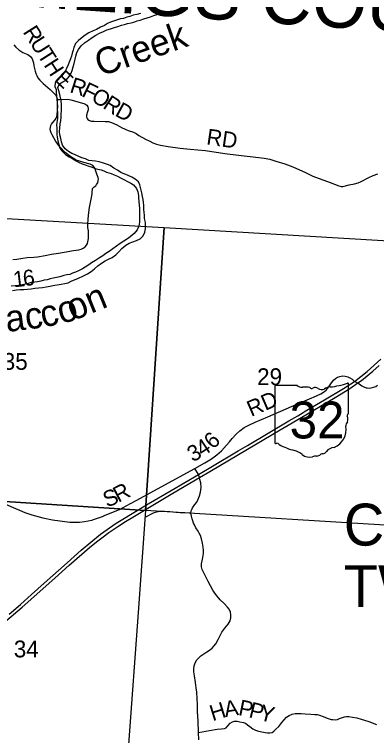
# Model space of a CAD drawing. Extents: x 0 to 34, y 0 to 22.
# Drawn here: x 4.807 to 6.101, y 18.062 to 20.64 of the extents above; entities that cross this region are included whole.
import ezdxf

# ---------------------------------------------------------------- set-up
doc = ezdxf.new("R2010")
doc.units = 0
for name, color, linetype in [('GM_X_Corporation', 7, 'Continuous'), ('GM_X_County_Road', 7, 'Continuous'), ('GM_X_County_Road_Text', 7, 'Continuous'), ('GM_X_County_Text', 7, 'Continuous'), ('GM_X_Major_River', 7, 'Continuous'), ('GM_X_Major_River_Text', 7, 'Continuous'), ('GM_X_Section_Text', 7, 'Continuous'), ('GM_X_State_Location', 7, 'Continuous'), ('GM_X_State_Route', 7, 'Continuous'), ('GM_X_State_Shield', 7, 'Continuous'), ('GM_X_Township_Road', 7, 'Continuous'), ('GM_X_Township_Road_Text', 7, 'Continuous'), ('GM_X_Township_Text', 7, 'Continuous')]:
    doc.layers.add(name, color=color, linetype=linetype)

msp = doc.modelspace()

# ---------------------------------------------------------------- linework, layer by layer
at = {"layer": 'GM_X_Corporation'}
for points in [[(5.342, 19.878), (5.2756, 18.8667), (4.2512, 18.9319), (4.3184, 19.9368)], [(6.3643, 19.8173), (6.291, 18.8048), (6.2863, 18.8051), (5.2756, 18.8667), (5.342, 19.878)], [(4.2512, 18.9319), (5.2756, 18.8667), (5.2491, 18.5021), (5.2146, 18.0305), (5.1989, 17.8285), (4.1811, 17.9012)]]:
    msp.add_lwpolyline(points, close=True, dxfattribs=at)
at = {"layer": 'GM_X_County_Road'}
msp.add_line((5.4645, 18.9957), (5.4516, 19.0172), dxfattribs=at)
for points in [[(5.8753, 19.272), (5.901, 19.2832), (5.9115, 19.2892), (5.9204, 19.2968), (5.9299, 19.3082), (5.9378, 19.3192), (5.9464, 19.3318), (5.9535, 19.3382), (5.9613, 19.3429), (5.9694, 19.3458), (5.9787, 19.3473), (5.9882, 19.3472), (5.9977, 19.3446), (6.0057, 19.3411), (6.013, 19.3358), (6.0224, 19.3279), (6.0334, 19.3224), (6.0481, 19.3119), (6.0549, 19.308), (6.0629, 19.3055), (6.0675, 19.3045), (6.0745, 19.3043), (6.0819, 19.3045), (6.0898, 19.3068), (6.0981, 19.3103), (6.1045, 19.3142)], [(5.5756, 19.1123), (5.5848, 19.1233), (5.5988, 19.139), (5.612, 19.1518), (5.6279, 19.1632), (5.6443, 19.1719), (5.6668, 19.1822), (5.7124, 19.2016), (5.7971, 19.2386), (5.8698, 19.2696), (5.8753, 19.272)], [(5.1256, 18.847), (5.182, 18.8697), (5.222, 18.891), (5.2441, 18.9036), (5.3055, 18.937), (5.4516, 19.0172), (5.4877, 19.0368), (5.5108, 19.0506), (5.5302, 19.0655), (5.5465, 19.0797), (5.5651, 19.0998), (5.5756, 19.1123)], [(4.7752, 18.8893), (4.8104, 18.8742), (4.8251, 18.8672), (4.8436, 18.8596), (4.8692, 18.8513), (4.9081, 18.8406), (4.943, 18.8337), (5.0054, 18.8244), (5.0211, 18.8242), (5.0396, 18.8244), (5.0574, 18.8267), (5.0834, 18.8321), (5.0929, 18.8354), (5.1247, 18.8467), (5.1256, 18.847)]]:
    msp.add_lwpolyline(points, dxfattribs=at)
at = {"layer": 'GM_X_Major_River'}
for points in [[(5.2579, 20.6426), (5.2439, 20.6395), (5.2314, 20.6368), (5.2197, 20.6326), (5.2091, 20.6296), (5.1962, 20.6257), (5.1864, 20.6238), (5.1501, 20.6116), (5.1395, 20.607), (5.1285, 20.6005), (5.1145, 20.594), (5.0998, 20.586), (5.0888, 20.5807), (5.0733, 20.5738), (5.0601, 20.5662), (5.0491, 20.5578), (5.0363, 20.5468), (5.0246, 20.5358), (5.0197, 20.521), (5.017, 20.5115), (5.0137, 20.5016), (5.011, 20.491), (5.0076, 20.4815), (5.0031, 20.4694), (4.999, 20.4599), (4.9933, 20.4462), (4.9865, 20.4344), (4.9767, 20.4207), (4.9639, 20.4086), (4.9526, 20.3953), (4.9515, 20.3816), (4.9556, 20.3714), (4.9564, 20.3615), (4.9568, 20.3487), (4.958, 20.3358), (4.9595, 20.3233), (4.9599, 20.3134), (4.96, 20.3009), (4.9604, 20.2884), (4.9604, 20.2679), (4.9589, 20.2531), (4.9578, 20.2436), (4.9582, 20.2342), (4.959, 20.2243), (4.9586, 20.2103), (4.9594, 20.2008), (4.9621, 20.1875), (4.9652, 20.1743), (4.9697, 20.1614), (4.9769, 20.1516), (4.9895, 20.1387), (5.002, 20.1308), (5.0156, 20.1232), (5.0274, 20.1165), (5.038, 20.1108), (5.049, 20.1059), (5.0596, 20.1018), (5.0725, 20.0969), (5.0842, 20.0939), (5.0956, 20.0894), (5.1054, 20.0867), (5.1164, 20.0837), (5.1266, 20.0807), (5.1365, 20.0762), (5.1524, 20.0709), (5.1634, 20.0668), (5.1755, 20.0611), (5.1857, 20.0559), (5.1982, 20.0495)], [(5.2501, 20.0416), (5.2384, 20.0511), (5.2259, 20.0579), (5.2137, 20.0635), (5.1872, 20.0748), (5.1751, 20.0828), (5.1622, 20.0903), (5.1489, 20.0994), (5.1391, 20.1035), (5.125, 20.1084), (5.1095, 20.1133), (5.0963, 20.1155), (5.0845, 20.1159), (5.0732, 20.1177), (5.061, 20.123), (5.0482, 20.1275), (5.0353, 20.1328), (5.0216, 20.1388), (5.0122, 20.1429), (4.9997, 20.1497), (4.9879, 20.1588), (4.9792, 20.172), (4.9746, 20.1838), (4.9727, 20.1967), (4.9696, 20.2088), (4.9685, 20.2217), (4.9688, 20.2334), (4.9707, 20.2486), (4.9722, 20.2596), (4.974, 20.2729), (4.9744, 20.2843), (4.9751, 20.2949), (4.9755, 20.3051), (4.9747, 20.318), (4.9735, 20.3309), (4.9689, 20.3536), (4.9655, 20.3665), (4.9617, 20.379), (4.9677, 20.3915), (4.9798, 20.3984), (4.9915, 20.4052), (5.0025, 20.4174), (5.0093, 20.4303), (5.0127, 20.4398), (5.0168, 20.4527), (5.0205, 20.4645), (5.0269, 20.4903), (5.0303, 20.5036), (5.036, 20.5146), (5.0454, 20.5271), (5.0575, 20.5381), (5.0711, 20.548), (5.0843, 20.5575), (5.0976, 20.5652), (5.1112, 20.5724), (5.1252, 20.5789), (5.1376, 20.5846), (5.1505, 20.5884), (5.1649, 20.5927), (5.1762, 20.5969), (5.1898, 20.6011), (5.2, 20.6037), (5.2114, 20.6072), (5.2235, 20.6099), (5.2333, 20.6126), (5.2454, 20.6171), (5.2564, 20.6198), (5.2689, 20.6237), (5.2814, 20.6271), (5.2935, 20.6313), (5.3048, 20.6355), (5.3169, 20.639), (5.3294, 20.6432)], [(5.1982, 20.0495), (5.2111, 20.0427), (5.2229, 20.0363), (5.2323, 20.0302), (5.243, 20.0174), (5.2475, 20.006), (5.2498, 19.9931), (5.2506, 19.9836), (5.2518, 19.9715), (5.2529, 19.9579), (5.2533, 19.9469), (5.2538, 19.9332), (5.2538, 19.8976), (5.2512, 19.8832), (5.2456, 19.8703), (5.235, 19.857), (5.221, 19.8444), (5.2104, 19.8379), (5.1843, 19.8204), (5.1715, 19.8113), (5.159, 19.8014), (5.1454, 19.7927), (5.1337, 19.785), (5.1224, 19.7763), (5.111, 19.7698), (5.0963, 19.7607), (5.0823, 19.7519), (5.0725, 19.7451), (5.06, 19.7367), (5.0502, 19.7306), (5.0354, 19.723), (5.0252, 19.7184), (5.015, 19.7149), (5.0052, 19.7104), (4.9938, 19.7084), (4.9836, 19.7061), (4.9688, 19.7019), (4.9579, 19.6996), (4.9458, 19.6969), (4.9352, 19.6946), (4.9238, 19.6916), (4.9132, 19.6893), (4.9011, 19.6866), (4.8898, 19.6843), (4.8799, 19.6831), (4.8671, 19.6812), (4.8561, 19.6785), (4.8402, 19.6746), (4.8296, 19.6723), (4.8198, 19.6708), (4.8092, 19.6692), (4.7955, 19.6681)], [(4.8005, 19.6533), (4.8141, 19.6552), (4.827, 19.6564), (4.8402, 19.6568), (4.8539, 19.6572), (4.8667, 19.6588), (4.88, 19.6607), (4.8925, 19.6619), (4.9076, 19.6642), (4.9208, 19.6662), (4.9341, 19.6685), (4.9447, 19.6708), (4.9734, 19.6754), (4.9867, 19.6781), (4.9995, 19.6804), (5.0098, 19.6857), (5.0237, 19.6918), (5.0336, 19.696), (5.054, 19.7052), (5.068, 19.7121), (5.0808, 19.7204), (5.0929, 19.7303), (5.105, 19.741), (5.1179, 19.7505), (5.1315, 19.7589), (5.1432, 19.765), (5.1561, 19.7703), (5.1689, 19.7802), (5.1802, 19.7909), (5.1908, 19.803), (5.2052, 19.8144), (5.2169, 19.8217), (5.2301, 19.8274), (5.2426, 19.832), (5.2559, 19.8373), (5.2664, 19.848), (5.2732, 19.8609), (5.2755, 19.8738), (5.2758, 19.8832), (5.2747, 19.8958), (5.2716, 19.9098), (5.2712, 19.9227), (5.2708, 19.9321), (5.2696, 19.9424), (5.2692, 19.9575), (5.2681, 19.9678), (5.2665, 19.978), (5.2646, 19.989), (5.2616, 20.0019), (5.2589, 20.0166), (5.2551, 20.0303), (5.2501, 20.0416)]]:
    msp.add_lwpolyline(points, dxfattribs=at)
at = {"layer": 'GM_X_State_Route'}
for points in [[(4.7883, 18.4958), (4.8282, 18.531), (4.8682, 18.5663), (4.9136, 18.6072), (4.995, 18.6797), (5.046, 18.7247), (5.0796, 18.7535), (5.1144, 18.7813), (5.1706, 18.8216), (5.1889, 18.8325), (5.2852, 18.89), (5.3667, 18.9378), (5.4645, 18.9957), (5.514, 19.0248), (5.6068, 19.0801), (5.6395, 19.099), (5.7872, 19.1867), (5.8197, 19.2052), (5.8287, 19.2112), (5.8517, 19.2248), (5.9148, 19.262), (5.982, 19.3023), (6.0224, 19.3279), (6.067, 19.3632), (6.1157, 19.408)], [(5.4683, 18.9843), (5.5047, 19.0058), (5.6072, 19.0664), (5.7568, 19.1545), (5.8482, 19.2086), (5.9525, 19.2702), (6.0054, 19.3027), (6.0334, 19.3224), (6.0463, 19.3315), (6.0665, 19.3473), (6.087, 19.3643), (6.1094, 19.3847)], [(4.2081, 18.3662), (4.3931, 18.3837), (4.5176, 18.395), (4.5827, 18.4009), (4.6096, 18.4044), (4.6234, 18.4073), (4.6449, 18.411), (4.6841, 18.4225), (4.7244, 18.4397), (4.7534, 18.4558), (4.7801, 18.4743), (4.8348, 18.5208), (4.9519, 18.6244), (5.0029, 18.6705), (5.0757, 18.7346), (5.1002, 18.7546), (5.1243, 18.7729), (5.1439, 18.7876), (5.1801, 18.8119), (5.2033, 18.8272), (5.2305, 18.8431), (5.3733, 18.9281), (5.4683, 18.9843)], [(5.4415, 18.8722), (5.4432, 18.8758), (5.4518, 18.888), (5.4582, 18.8968), (5.4635, 18.9072), (5.4687, 18.919), (5.4717, 18.9315), (5.4738, 18.949), (5.4723, 18.9649), (5.4696, 18.9774), (5.4683, 18.9843), (5.4645, 18.9957)], [(5.4654, 18.0462), (5.4648, 18.0726), (5.4631, 18.1142), (5.4615, 18.1468), (5.4609, 18.1736), (5.4599, 18.1933), (5.4585, 18.2168), (5.4564, 18.2327), (5.4542, 18.2517), (5.4497, 18.2757), (5.4487, 18.2825), (5.4483, 18.29), (5.4481, 18.3006), (5.4495, 18.3108), (5.4529, 18.3222), (5.4587, 18.3324), (5.4672, 18.3414), (5.4731, 18.3469), (5.4941, 18.3608), (5.5043, 18.3669), (5.5131, 18.3742), (5.5194, 18.381), (5.526, 18.3895), (5.5345, 18.4059), (5.5427, 18.4226), (5.5484, 18.432), (5.5586, 18.4454), (5.5707, 18.46), (5.5778, 18.4721), (5.5802, 18.483), (5.5804, 18.493), (5.5786, 18.5029), (5.5741, 18.5142), (5.5684, 18.5215), (5.5562, 18.5335), (5.5419, 18.5476), (5.5309, 18.5599), (5.5225, 18.5713), (5.5154, 18.5817), (5.4992, 18.6121), (5.4819, 18.6455), (5.4776, 18.6561), (5.4758, 18.6649), (5.4752, 18.6763), (5.4772, 18.6869), (5.4797, 18.6985), (5.4823, 18.7124), (5.4829, 18.723), (5.4815, 18.7355), (5.4789, 18.7495), (5.4748, 18.7654), (5.4713, 18.7767), (5.4672, 18.7856), (5.4635, 18.7928), (5.4556, 18.8046), (5.4497, 18.8152), (5.4466, 18.8215), (5.4438, 18.8293), (5.4417, 18.8364), (5.4391, 18.8468), (5.4377, 18.8571), (5.4385, 18.8658), (5.4415, 18.8722)]]:
    msp.add_lwpolyline(points, dxfattribs=at)
at = {"layer": 'GM_X_State_Shield'}
for p, q in [((5.7369, 19.3101), (5.7369, 19.1099)), ((5.8167, 19.3135), (5.7395, 19.3135)), ((6.0006, 19.2138), (6.0006, 19.3185)), ((6.0006, 19.2138), (6.0006, 19.2138))]:
    msp.add_line(p, q, dxfattribs=at)
for centre, radius, start, end in [((5.74, 19.3105), 0.00305, 98.1301, 188.1301), ((5.8351, 19.3367), 0.0296, 231.6195, 271.1119), ((5.9067, 19.5863), 0.2796, 275.8445, 288.9065), ((5.9977, 19.3189), 0.00294, 351.8621, 97.738), ((5.845, 19.2012), 0.1064, 80.4867, 94.9883), ((5.8691, 19.3115), 0.00855, 219.7921, 297.1024), ((5.8816, 19.2884), 0.0178, 54.4667, 119.1411), ((5.9046, 19.3201), 0.0214, 233.8562, 294.8282), ((5.9423, 19.2524), 0.0563, 97.3462, 120.7689), ((5.9999, 19.2061), 0.00454, 107.944, 210.337), ((5.9975, 19.2134), 0.00314, 289.6038, 7.7341), ((6.0111, 19.17), 0.0198, 136.8065, 186.9296), ((5.971, 19.1929), 0.0273, 340.033, 23.6496), ((5.9223, 19.1567), 0.0699, 292.3089, 8.9858), ((5.74, 19.1095), 0.00308, 171.9584, 258.3066), ((5.7404, 19.13), 0.0235, 267.339, 280.6039), ((5.7453, 19.0984), 0.00848, 29.7484, 93.2717), ((5.8523, 19.2782), 0.2019, 240.4129, 257.1985), ((5.7921, 19.02), 0.0632, 47.1842, 75.836), ((5.9033, 19.0906), 0.0226, 282.8732, 323.2771), ((5.9518, 19.0538), 0.0383, 94.4031, 142.5768), ((5.8604, 19.0974), 0.0401, 230.7004, 286.2918), ((5.8836, 19.0282), 0.0329, 85.6951, 111.2099), ((5.8865, 19.0824), 0.0214, 268.777, 315.5493), ((5.9059, 19.063), 0.00601, 65.7517, 132.6484)]:
    msp.add_arc(centre, radius, start, end, dxfattribs=at)
at = {"layer": 'GM_X_Township_Road'}
for points in [[(4.8051, 20.5316), (4.8119, 20.5227), (4.8222, 20.5135), (4.837, 20.5038), (4.8547, 20.4961), (4.8639, 20.4894), (4.87, 20.4809), (4.8729, 20.4736), (4.8746, 20.4664), (4.8769, 20.4558), (4.8808, 20.4369), (4.8829, 20.4288), (4.8866, 20.421), (4.8909, 20.4136), (4.8983, 20.4042), (4.9092, 20.3924), (4.9341, 20.371), (4.9453, 20.3606), (4.9534, 20.3523), (4.9562, 20.3488), (4.9576, 20.3447), (4.9613, 20.3362), (4.9686, 20.336), (4.9968, 20.3366), (5.0083, 20.3347), (5.0379, 20.3264), (5.0587, 20.3204), (5.0655, 20.3156), (5.0689, 20.3099), (5.0702, 20.304), (5.0699, 20.2989), (5.0675, 20.2913), (5.0641, 20.2802), (5.0647, 20.2724), (5.0664, 20.2676), (5.0692, 20.2642), (5.0732, 20.2614), (5.0811, 20.2587), (5.0924, 20.2577), (5.1312, 20.257), (5.1429, 20.2567), (5.1533, 20.2536), (5.1727, 20.2451), (5.1897, 20.236), (5.2028, 20.2294), (5.2137, 20.2247), (5.2322, 20.2189), (5.2424, 20.2139), (5.2517, 20.2066), (5.2754, 20.1938), (5.2904, 20.1867), (5.3019, 20.1812), (5.3145, 20.1763), (5.3291, 20.1723), (5.3557, 20.1676), (5.3996, 20.1618), (5.435, 20.1578), (5.4901, 20.153), (5.5581, 20.1427), (5.6078, 20.1362), (5.6803, 20.1282), (5.6997, 20.1258), (5.7193, 20.1222), (5.7409, 20.1158), (5.7734, 20.106), (5.8021, 20.0945), (5.847, 20.0753), (5.8728, 20.0618), (5.9347, 20.0392), (5.9653, 20.027), (5.9742, 20.0251), (5.9804, 20.025), (6.0028, 20.0305), (6.0215, 20.0341), (6.0348, 20.0375), (6.0462, 20.0427), (6.0725, 20.0572), (6.0885, 20.0641), (6.1048, 20.0698)], [(4.8017, 19.7637), (4.8162, 19.7645), (4.8368, 19.768), (4.8529, 19.7703), (4.8764, 19.772), (4.8896, 19.7733), (4.917, 19.7779), (4.9394, 19.7828), (4.9643, 19.7864), (4.9843, 19.7895), (5.0182, 19.7959), (5.0376, 19.7987), (5.0457, 19.8008), (5.0521, 19.8038), (5.0599, 19.8088), (5.0646, 19.8146), (5.0678, 19.8211), (5.0698, 19.8271), (5.0714, 19.8392), (5.0721, 19.8533), (5.0714, 19.8663), (5.0698, 19.8782), (5.0691, 19.8904), (5.0701, 19.9064), (5.0715, 19.9218), (5.0749, 19.9497), (5.0795, 19.973), (5.0796, 19.9737), (5.0832, 19.9914), (5.0842, 20.0002), (5.0846, 20.0067), (5.0855, 20.0127), (5.0864, 20.017), (5.0883, 20.0203), (5.0924, 20.0235), (5.0973, 20.0269), (5.1007, 20.0315), (5.1044, 20.038), (5.1067, 20.0456), (5.1074, 20.0509), (5.1063, 20.0574), (5.1012, 20.0689), (5.0975, 20.0795), (5.0957, 20.0876), (5.0924, 20.094), (5.0869, 20.0994), (5.0779, 20.1042), (5.0546, 20.1104), (5.0281, 20.1192), (5.008, 20.1303), (4.9887, 20.1462), (4.9703, 20.1653), (4.9546, 20.1861), (4.9416, 20.2095), (4.9379, 20.217), (4.9363, 20.2241), (4.9352, 20.2301), (4.9357, 20.2358), (4.9368, 20.2425), (4.9398, 20.2478), (4.9437, 20.2536), (4.9523, 20.2626), (4.9567, 20.2688), (4.9583, 20.2739), (4.9598, 20.282), (4.9608, 20.2958), (4.9615, 20.3105), (4.9613, 20.3239), (4.9613, 20.3362)], [(5.4377, 18.8571), (5.4153, 18.8576), (5.3986, 18.8576), (5.3833, 18.8595), (5.3744, 18.8603), (5.3618, 18.8618), (5.3433, 18.8625), (5.332, 18.8625), (5.3204, 18.8618), (5.31, 18.8595), (5.3029, 18.8571), (5.295, 18.8536), (5.2824, 18.8467), (5.2755, 18.8428)], [(5.4648, 18.0726), (5.5037, 18.0799), (5.5315, 18.0848), (5.5462, 18.0857), (5.5576, 18.0871), (5.5631, 18.0899), (5.5696, 18.0973), (5.5772, 18.1064), (5.5855, 18.1115), (5.5929, 18.1134), (5.6026, 18.1132), (5.6126, 18.1115), (5.6251, 18.1089), (5.6322, 18.1058), (5.64, 18.1007), (5.6485, 18.0948), (5.6591, 18.0857), (5.6683, 18.0816), (5.6783, 18.0781), (5.691, 18.0748), (5.7024, 18.0732), (5.7112, 18.072), (5.7197, 18.0722), (5.7273, 18.0734), (5.7342, 18.0779), (5.7413, 18.0844), (5.7513, 18.0948), (5.7628, 18.1091), (5.7787, 18.1275), (5.7887, 18.1342), (5.7989, 18.1385), (5.8099, 18.1411), (5.8205, 18.1411), (5.8313, 18.1411), (5.8452, 18.1401), (5.8664, 18.1389), (5.8796, 18.1373), (5.8882, 18.137), (5.897, 18.135), (5.9102, 18.1303), (5.9239, 18.124), (5.9318, 18.1213), (5.9386, 18.1197), (5.9447, 18.1189), (5.9526, 18.1187), (5.9616, 18.1197), (5.9686, 18.1228), (5.9785, 18.1266), (5.9855, 18.1293), (5.9934, 18.1305), (6.0014, 18.1305), (6.0142, 18.1283), (6.0303, 18.1254), (6.0454, 18.1211), (6.0579, 18.1173), (6.0732, 18.1122), (6.1007, 18.1016)]]:
    msp.add_lwpolyline(points, dxfattribs=at)

# ---------------------------------------------------------------- texts
at = {"layer": 'GM_X_County_Road_Text'}
for s, height, rotation, p in [('RD', 0.05682, 23.2643, (5.6527, 19.2007)), ('6', 0.0568, 42.7907, (5.5158, 19.083)), ('3', 0.0568, 29.0852, (5.4441, 19.0381)), ('4', 0.0568, 33.3694, (5.4786, 19.0575)), ('R', 0.0568, 27.8588, (5.1783, 18.8934)), ('S', 0.0568, 22.78, (5.1379, 18.8762))]:
    msp.add_text(s, height=height, rotation=rotation, dxfattribs=at).set_placement(p)
at = {"layer": 'GM_X_County_Text'}
msp.add_text('MEIGS COUNTY', height=0.189394, rotation=356.1113, dxfattribs=at).set_placement((4.7976, 20.6717))
at = {"layer": 'GM_X_Major_River_Text'}
for s, height, rotation, p in [('Creek', 0.0947, 19.0988, (5.1136, 20.417)), ('on', 0.09469, 22.0989, (5.0152, 19.5431)), ('co', 0.0947, 13.1008, (4.9098, 19.5195)), ('ac', 0.0947, 7.102, (4.7799, 19.5044))]:
    msp.add_text(s, height=height, rotation=rotation, dxfattribs=at).set_placement(p)
at = {"layer": 'GM_X_Section_Text'}
for s, p in [('35', (4.7652, 19.3694)), ('29', (5.6739, 19.3148)), ('34', (4.8048, 18.3415))]:
    msp.add_text(s, height=0.06, rotation=0, dxfattribs=at).set_placement(p)
at = {"layer": 'GM_X_State_Location'}
msp.add_text('32', height=0.000189, rotation=0, dxfattribs=at).set_placement((5.8181, 19.1829))
for s in ['s', 'r']:
    msp.add_text(s, height=0.000189, dxfattribs=at).set_placement((5.8658, 19.1967))
at = {"layer": 'GM_X_State_Shield'}
msp.add_text('32', height=0.13184, dxfattribs=at).set_placement((5.7901, 19.1241))
at = {"layer": 'GM_X_Township_Road_Text'}
for s, height, rotation, p in [('R', 0.0568, 302.319, (4.8354, 20.5771)), ('U', 0.0568, 302.3208, (4.8603, 20.5377)), ('T', 0.0568, 302.3207, (4.887, 20.4954)), ('H', 0.0568, 302.7166, (4.91, 20.4591)), ('E', 0.0568, 317.0494, (4.9469, 20.4052)), ('R', 0.0568, 342.3324, (5.0015, 20.3625)), ('F', 0.0568, 334.5123, (5.0441, 20.3491)), ('O', 0.0568, 328.0894, (5.0772, 20.3334)), ('R', 0.0568, 327.0439, (5.1194, 20.3071)), ('D', 0.0568, 331.5761, (5.1628, 20.2793)), ('RD', 0.05682, 351.7984, (5.4908, 20.1756)), ('1', 0.0568, 6.5284, (4.8053, 19.6641)), ('6', 0.0568, 6.8816, (4.8405, 19.6681)), ('H', 0.0568, 17.2645, (5.5148, 18.1132)), ('A', 0.0568, 9.1383, (5.5604, 18.1275)), ('P', 0.0568, 348.4958, (5.6044, 18.1356)), ('P', 0.0568, 346.0456, (5.6414, 18.1281)), ('Y', 0.0568, 345.8688, (5.6785, 18.1188))]:
    msp.add_text(s, height=height, rotation=rotation, dxfattribs=at).set_placement(p)
at = {"layer": 'GM_X_Township_Text'}
for s, p in [('COLUMBIA', (5.9834, 18.741)), ('TWP.', (5.9834, 18.521))]:
    msp.add_text(s, height=0.15, rotation=0, dxfattribs=at).set_placement(p)

doc.saveas('drawing.dxf')
